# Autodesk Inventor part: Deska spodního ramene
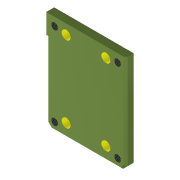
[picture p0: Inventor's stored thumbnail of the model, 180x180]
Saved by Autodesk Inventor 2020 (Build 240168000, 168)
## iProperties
Created: 2025-03
Part Number: Deska spodního ramene
Material: Ocel
Document SubType Name: Modeling
Designer: doma
Density: 7.85 g/cm^3
Appearance: Tmavě olivová
Mass: 1660.76 g
Surface Area: 431.658 cm^2
Volume: 211.562 cm^3
Author: doma
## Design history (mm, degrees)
sketch "Náčrt1"
  geometry: L1 (0, 0)-(-120, 0); L2 (-120, 0)-(-120, 150); L3 (-120, 150)-(0, 150); L4 (0, 150)-(0, 0)
  constraints: 8 end point, 2 parallel, 1 horizontal, 1 perpendicular
  dimensions: "d0" = 120 distance of L2.end L3.end; "d1" = 150 distance of L1.end L2.end
extrude "Vysunutí1" new body sketch "Náčrt1" distance "d2" = 12; taper "d3" = 0 deg
chamfer "Zkosení1" distance "d4" = 7; stored, may be unused: second distance "d5" = 2, angle "d6" = 45 deg
sketch "Náčrt2"
  geometry: L1 (117.5, 9.5)-(110.5, 2.5) reference; L2 (117.5, 9.5)-(117.5, 147.5) reference; L3 (117.5, 147.5)-(2.5, 147.5) reference; L4 (2.5, 147.5)-(2.5, 9.5) reference; L5 (9.5, 2.5)-(2.5, 9.5) reference; L6 (9.5, 2.5)-(110.5, 2.5) reference; C1 r 6.75 at (12.5, 12.5) reference; C2 r 6.75 at (12.5, 137.5) reference; C3 r 6.75 at (107.5, 12.5) reference; C4 r 6.75 at (12.5, 137.5) reference; C5 r 6.75 at (12.5, 12.5) reference; C6 r 6.75 at (107.5, 137.5) reference; C7 r 6.75 at (107.5, 12.5) reference; 5 further points
  constraints: 4 coincident
hole "Díra1" sketch "Náčrt2" at (107.5, 137.5), (107.5, 12.5), (12.5, 12.5), (12.5, 137.5) diameter "d7" = 10.106; stored, may be unused: countersink angle "d11" = 90 deg, drill point angle "d13" = 118 deg; dims "d8" = 24, "d9" = 4, "d10" = 2, "d12" = 8
sketch "Náčrt3"
  geometry: L1 (0, 150)-(120, 150) reference; L2 (0, 7)-(0, 150) reference; L3 (90, 135)-(30, 135); L4 (30, 135)-(30, 20); L5 (30, 20)-(90, 20); L6 (90, 20)-(90, 135); C1 r 6.75 at (90, 20); C2 r 6.75 at (30, 20); C3 r 6.75 at (90, 135); C4 r 6.75 at (30, 135); 1 further point
  constraints: 8 end point, 4 centre point, 1 horizontal, 1 perpendicular
  dimensions: "d14" = 115 distance of L5.end L3.start; "d15" = 60 distance of L4.end L5.end; "d16" = 115 distance of L4.end L3.end; "d17" = 60 distance of L3.start L3.end; "d18" = 15 distance from line of L1 L3.end; "d19" = 30 distance from line of L2 L3.end
extrude "Vysunutí2" cut sketch "Náčrt3" extent not by distance; stored distance "d20" = 0; taper "d21" = 0 deg
chamfer "Zkosení2" distance "d22" = 3; stored, may be unused: second distance "d23" = 2, angle "d24" = 45 deg
chamfer "Zkosení3" distance "d25" = 3; stored, may be unused: second distance "d26" = 2, angle "d27" = 45 deg; dims "d28" = 30, "d29" = 108.75736, "d30" = 0 (derived)
node "Těleso1"
node "Referenční1"
node "Referenční2"
node "Referenční3"
node "Referenční4"
